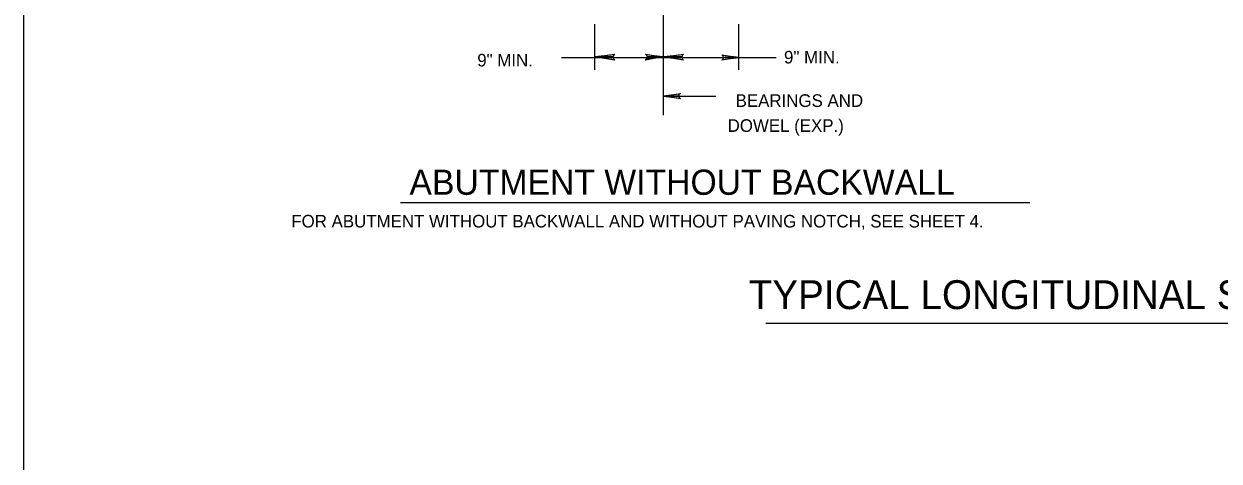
# Model space of a CAD drawing. Extents: x 638653 to 642302, y 298557 to 300414.
# Drawn here: x 640704.2 to 640988.5, y 300037.8 to 300141.8 of the extents above; entities that cross this region are included whole.
import ezdxf

# ---------------------------------------------------------------- set-up
doc = ezdxf.new("R2010")
doc.units = 0
doc.layers.add('1', color=7, linetype='Continuous')

msp = doc.modelspace()

# ---------------------------------------------------------------- linework, layer by layer
at = {"layer": '1'}
for p, q in [((640704.16, 299759.52), (640704.16, 300323.52)), ((640856.27, 300213.72), (640856.27, 300120.11)), ((640840.02, 300130.88), (640840.02, 300141.69)), ((640874.24, 300130.88), (640874.24, 300141.69)), ((640832.06, 300133.79), (640883.15, 300133.79)), ((640856.27, 300124.57), (640868.77, 300124.57)), ((640943.52, 300099.25), (640793.77, 300099.25)), ((640880.66, 300070.56), (641307.03, 300070.56))]:
    msp.add_line(p, q, dxfattribs=at)
for points in [[(640844.56, 300133.32), (640844.4, 300133.63), (640840.02, 300133.95), (640844.56, 300133.32), (640844.71, 300133.17), (640840.02, 300133.95), (640844.4, 300134.1), (640844.56, 300134.42), (640840.02, 300133.95), (640844.71, 300134.57), (640844.56, 300134.42)], [(640852.21, 300134.42), (640852.37, 300134.1), (640856.12, 300133.95), (640852.21, 300134.42), (640852.06, 300134.57), (640856.12, 300133.95), (640852.37, 300133.63), (640852.21, 300133.48), (640856.12, 300133.95), (640852.06, 300133.17), (640852.21, 300133.48)], [(640860.96, 300133.32), (640860.81, 300133.63), (640856.43, 300133.95), (640860.96, 300133.32), (640861.12, 300133.17), (640856.43, 300133.95), (640860.81, 300134.1), (640860.96, 300134.42), (640856.43, 300133.95), (640861.12, 300134.57), (640860.96, 300134.42)], [(640870.34, 300134.26), (640870.49, 300133.95), (640874.24, 300133.79), (640870.34, 300134.26), (640870.18, 300134.42), (640874.24, 300133.79), (640870.49, 300133.63), (640870.34, 300133.32), (640874.24, 300133.79), (640870.18, 300133.17), (640870.34, 300133.32)], [(640860.18, 300124.1), (640860.02, 300124.41), (640856.27, 300124.57), (640860.18, 300124.1), (640860.34, 300123.94), (640856.27, 300124.57), (640860.02, 300124.72), (640860.02, 300125.04), (640856.27, 300124.57), (640860.34, 300125.19), (640860.02, 300125.04)]]:
    msp.add_lwpolyline(points, dxfattribs=at)

# ---------------------------------------------------------------- texts
for s, height, p in [('9" MIN.', 3, (640812.02, 300131.66)), ('9" MIN.', 3, (640885, 300132.37)), ('  BEARINGS AND', 3, (640871.27, 300122.04)), ('DOWEL (EXP.)', 3, (640871.59, 300116.1)), ('ABUTMENT WITHOUT BACKWALL', 6, (640795.89, 300101.12)), ('FOR ABUTMENT WITHOUT BACKWALL AND WITHOUT PAVING NOTCH, SEE SHEET 4.', 3, (640767.78, 300093.35)), ('TYPICAL LONGITUDINAL SECTIONS FOR ADJACENT BOX BEAMS (COMPOSITE)', 6.8753, (640876.59, 300073.93))]:
    msp.add_text(s, height=height, dxfattribs=at).set_placement(p)

doc.saveas('drawing.dxf')
